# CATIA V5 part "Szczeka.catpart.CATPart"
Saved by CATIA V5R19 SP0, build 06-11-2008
Part number: Szczeka
Revision: ANY
Definition: Jaw
Source: Unknown
Bounding box of the stored display mesh (mm): x 0 to 125, y 0 to 109, z -18 to 105.893
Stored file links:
  G:\Catia\CD\Ustawienia\Imadlo\Szczeka.catpart.CATPart
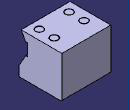
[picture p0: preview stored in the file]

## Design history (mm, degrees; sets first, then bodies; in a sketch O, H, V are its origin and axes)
Set1
  Sketch1 on face of Solid1, origin (125, 0, 0), H (0, 1, 0), V (0, 0, 1)
    line L1 (-12.8632, 127.7508) -> (122.5616, 127.7508)
    line L2 (122.5616, 127.7508) -> (122.5616, 105.8928)
    line L3 (122.5616, 105.8928) -> (-12.8632, 105.8928)
    line L4 (-12.8632, 105.8928) -> (-12.8632, 127.7508)
    horizontal: L1 H, L3 H
    vertical: L2 V, L4 V
Body1 "Imported1" (main body)
  Solid1 "Manifold Solid #2513": solid without history
  Pocket1: profile Sketch1, direction (-1, 0, 0), through (limit type 6)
